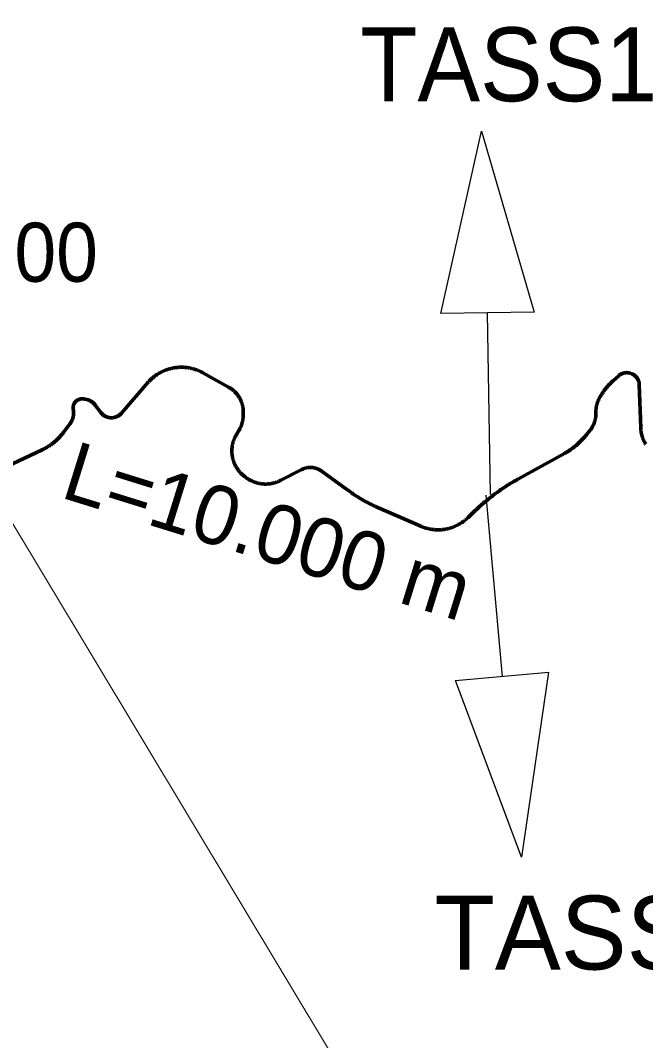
# Model space of a CAD drawing. Extents: x -1643653 to 4543381, y 1624270 to 13878484.
# Drawn here: x 592913 to 597147, y 8961770 to 8968678 of the extents above; entities that cross this region are included whole.
import ezdxf
from ezdxf.enums import TextEntityAlignment as Align

# ---------------------------------------------------------------- set-up
doc = ezdxf.new("R2010")
doc.units = 0
doc.header["$LTSCALE"] = 160
for name, color, linetype, lineweight in [('15', 7, 'Continuous', 25), ('50', 7, 'Continuous', 13), ('54', 7, 'Continuous', 25), ('60', 7, 'Continuous', 13), ('61', 7, 'Continuous', 70)]:
    doc.layers.add(name, color=color, linetype=linetype, lineweight=lineweight)

msp = doc.modelspace()

# ---------------------------------------------------------------- linework, layer by layer
at = {"layer": '50'}
msp.add_lwpolyline([(592100.1, 8966535.4), (596008.5, 8960032.9), (592886.1, 8960032.9)], dxfattribs=at)
at = {"layer": '54'}
for p, q in [((596096.5, 8965467.2), (596076.8, 8966698.1)), ((596064.8, 8965462.2), (596175, 8964236.1))]:
    msp.add_line(p, q, dxfattribs=at)
for points in [[(595761, 8966693.1), (596034.8, 8967928.7), (596392.5, 8966703.2)], [(596489.5, 8964264.3), (596307.4, 8963011.9), (595860.5, 8964207.8)]]:
    msp.add_lwpolyline(points, close=True, dxfattribs=at)
at = {"layer": '60', "lineweight": 25}
msp.add_spline([(814781, 9009175.5), (814787.2, 9009173.4), (814796.9, 9009173.4), (814799.4, 9009172.4), (814805.1, 9009174.5), (814805.6, 9009176.5), (814811.7, 9009179.5), (814811.7, 9009179.5), (814801.5, 9009181), (814790.7, 9009181.5), (814784.1, 9009183.1), (814777.4, 9009185.1), (814778.4, 9009175.5)], degree=3, dxfattribs=at)
at = {"layer": '61'}
for points in [[(593875.9, 8966300.6), (593871.5, 8966298.5), (593867.1, 8966296.3), (593862.8, 8966294), (593858.5, 8966291.7), (593854.2, 8966289.3), (593850, 8966286.8), (593845.8, 8966284.3), (593841.6, 8966281.7), (593837.5, 8966279), (593833.5, 8966276.3), (593829.4, 8966273.5), (593825.5, 8966270.6), (593821.6, 8966267.6), (593817.7, 8966264.6), (593813.9, 8966261.6), (593810.1, 8966258.5), (593806.4, 8966255.3), (593802.7, 8966252), (593799.1, 8966248.7), (593795.5, 8966245.3), (593792, 8966241.9), (593788.6, 8966238.4), (593785.2, 8966234.9), (593781.9, 8966231.3), (593778.6, 8966227.7), (593776.4, 8966225.2), (593597.7, 8966018.2), (593595.9, 8966016.2), (593594.1, 8966014.3), (593592.2, 8966012.4), (593590.2, 8966010.5), (593588.2, 8966008.8), (593586.2, 8966007), (593584.1, 8966005.4), (593581.9, 8966003.8), (593579.7, 8966002.3), (593577.4, 8966000.8), (593575.1, 8965999.4), (593572.8, 8965998.1), (593570.4, 8965996.8), (593568, 8965995.7), (593565.6, 8965994.5), (593563.1, 8965993.5), (593560.6, 8965992.5), (593558.1, 8965991.7), (593555.5, 8965990.8), (593552.9, 8965990.1), (593550.3, 8965989.5), (593547.7, 8965988.9), (593545.1, 8965988.4), (593542.4, 8965988), (593539.8, 8965987.6), (593537.1, 8965987.3), (593534.4, 8965987.2), (593531.7, 8965987.1), (593529.1, 8965987), (593526.4, 8965987.1), (593523.7, 8965987.2), (593521, 8965987.4), (593518.3, 8965987.7), (593515.7, 8965988.1), (593513, 8965988.6), (593510.4, 8965989.1), (593507.8, 8965989.7), (593505.2, 8965990.4), (593502.6, 8965991.2), (593500.1, 8965992), (593497.6, 8965992.9), (593495.1, 8965993.9), (593492.6, 8965995), (593490.2, 8965996.1), (593487.8, 8965997.3), (593485.4, 8965998.6), (593483.1, 8966000), (593480.8, 8966001.4), (593478.6, 8966002.9), (593476.4, 8966004.4), (593474.3, 8966006.1), (593472.2, 8966007.7), (593470.1, 8966009.5), (593468.2, 8966011.3), (593466.2, 8966013.1), (593464.3, 8966015.1), (593462.5, 8966017), (593460.8, 8966019.1), (593459.1, 8966021.1), (593457.8, 8966022.7), (593419.8, 8966073), (593418, 8966075.2), (593416.2, 8966077.5), (593414.3, 8966079.7), (593412.3, 8966081.8), (593410.3, 8966083.9), (593408.2, 8966085.9), (593406.1, 8966087.8), (593403.9, 8966089.8), (593401.6, 8966091.6), (593399.3, 8966093.4), (593397, 8966095.1), (593394.6, 8966096.7)], [(594416.1, 8966074.9), (594415, 8966078.7), (594413.9, 8966082.5), (594412.7, 8966086.3), (594411.4, 8966090), (594410, 8966093.7), (594408.6, 8966097.4), (594407.1, 8966101), (594405.5, 8966104.6), (594403.8, 8966108.2), (594402.1, 8966111.8), (594400.3, 8966115.3), (594398.4, 8966118.8), (594396.5, 8966122.2), (594394.4, 8966125.6), (594392.4, 8966129), (594390.2, 8966132.3), (594388, 8966135.5), (594385.7, 8966138.8), (594383.4, 8966141.9), (594381, 8966145.1), (594378.5, 8966148.1), (594375.9, 8966151.2), (594373.3, 8966154.1), (594370.7, 8966157.1), (594368, 8966159.9), (594365.2, 8966162.7), (594362.4, 8966165.5), (594359.5, 8966168.2), (594356.5, 8966170.8), (594353.5, 8966173.4), (594350.5, 8966175.9), (594347.4, 8966178.4), (594344.3, 8966180.8), (594341.1, 8966183.1), (594337.8, 8966185.4), (594334.6, 8966187.6), (594331.2, 8966189.7), (594327.9, 8966191.8), (594324.5, 8966193.8), (594322.6, 8966194.8), (594322.6, 8966194.8), (594149.4, 8966291.2), (594145.1, 8966293.6), (594140.7, 8966295.8), (594136.4, 8966298), (594132, 8966300.2), (594127.5, 8966302.2), (594123, 8966304.2), (594118.5, 8966306.1), (594114, 8966308), (594109.4, 8966309.8), (594104.8, 8966311.4), (594100.2, 8966313.1), (594095.6, 8966314.6), (594090.9, 8966316.1), (594086.2, 8966317.5), (594081.5, 8966318.8), (594076.7, 8966320), (594072, 8966321.2), (594067.2, 8966322.2), (594062.4, 8966323.2), (594057.6, 8966324.2), (594052.8, 8966325), (594047.9, 8966325.8), (594043.1, 8966326.5), (594038.2, 8966327.1), (594033.3, 8966327.6), (594028.5, 8966328), (594023.6, 8966328.4), (594018.7, 8966328.7), (594013.8, 8966328.9), (594008.9, 8966329), (594004, 8966329.1), (593999.1, 8966329.1), (593994.2, 8966328.9), (593989.3, 8966328.8), (593984.4, 8966328.5), (593979.5, 8966328.1), (593974.6, 8966327.7), (593969.8, 8966327.2), (593964.9, 8966326.6), (593960, 8966325.9), (593955.2, 8966325.2), (593950.4, 8966324.3), (593945.6, 8966323.4), (593940.8, 8966322.5), (593936, 8966321.4), (593931.2, 8966320.3), (593926.5, 8966319), (593921.7, 8966317.7), (593917, 8966316.4), (593912.4, 8966314.9), (593907.7, 8966313.4), (593903.1, 8966311.8), (593898.5, 8966310.1), (593893.9, 8966308.4), (593889.3, 8966306.5), (593884.8, 8966304.6), (593880.3, 8966302.7), (593875.9, 8966300.6)], [(597148.7, 8965807.3), (597146.4, 8965810.8), (597144.2, 8965814.4), (597142.2, 8965818), (597140.1, 8965821.6), (597138.2, 8965825.2), (597136.3, 8965828.9), (597134.5, 8965832.6), (597132.7, 8965836.4), (597131, 8965840.2), (597129.4, 8965844), (597127.9, 8965847.9), (597126.5, 8965851.8), (597125.1, 8965855.7), (597123.8, 8965859.6), (597122.6, 8965863.6), (597121.4, 8965867.6), (597120.3, 8965871.6), (597119.3, 8965875.6), (597118.4, 8965879.6), (597117.6, 8965883.7), (597116.8, 8965887.8), (597116.2, 8965891.9), (597115.6, 8965896), (597115.1, 8965900.1), (597114.6, 8965904.2), (597114.2, 8965908.3), (597114, 8965912.5), (597113.8, 8965916.6), (597113.7, 8965917.8), (597103.8, 8966212.4), (597103.7, 8966215), (597103.5, 8966217.5), (597103.2, 8966220), (597102.8, 8966222.5), (597102.4, 8966225), (597101.9, 8966227.5), (597101.3, 8966229.9), (597100.6, 8966232.3), (597099.9, 8966234.8), (597099, 8966237.2), (597098.1, 8966239.5), (597097.2, 8966241.8), (597096.1, 8966244.2), (597095, 8966246.4), (597093.8, 8966248.6), (597092.5, 8966250.8), (597091.2, 8966253), (597089.8, 8966255.1), (597088.3, 8966257.2), (597086.8, 8966259.2), (597085.2, 8966261.1), (597083.5, 8966263), (597081.8, 8966264.9), (597080, 8966266.7), (597078.2, 8966268.5), (597076.3, 8966270.1), (597074.4, 8966271.8), (597072.4, 8966273.3), (597070.4, 8966274.8), (597068.3, 8966276.3), (597066.2, 8966277.7), (597064, 8966279), (597061.8, 8966280.2), (597059.5, 8966281.3), (597057.3, 8966282.4), (597054.9, 8966283.5), (597052.6, 8966284.4), (597050.5, 8966285.2), (597050.5, 8966285.2), (597041.8, 8966288.2), (597039.5, 8966289), (597037.2, 8966289.7), (597034.8, 8966290.3), (597032.4, 8966290.9), (597030, 8966291.4), (597027.6, 8966291.8), (597025.1, 8966292.1), (597022.7, 8966292.3), (597020.3, 8966292.4), (597017.8, 8966292.5), (597015.4, 8966292.5), (597012.9, 8966292.4), (597010.5, 8966292.2), (597008, 8966292), (597005.6, 8966291.7), (597003.2, 8966291.3), (597000.8, 8966290.8), (596998.4, 8966290.2), (596996, 8966289.6), (596993.7, 8966288.8), (596991.4, 8966288.1), (596989.1, 8966287.2), (596986.8, 8966286.2), (596984.6, 8966285.2), (596982.4, 8966284.1), (596980.2, 8966283), (596978.1, 8966281.8), (596976.1, 8966280.5), (596974, 8966279.1), (596972, 8966277.7)], [(596972, 8966277.7), (596970.1, 8966276.2), (596968.2, 8966274.6), (596966.9, 8966273.5), (596966.9, 8966273.5), (596927.1, 8966238), (596927.1, 8966238), (596922.8, 8966234), (596918.5, 8966230), (596914.2, 8966226), (596910.1, 8966221.9), (596905.9, 8966217.7), (596901.9, 8966213.5), (596897.8, 8966209.2), (596893.9, 8966204.9), (596890, 8966200.5), (596886.2, 8966196), (596882.4, 8966191.6), (596878.7, 8966187), (596875, 8966182.4), (596871.4, 8966177.8), (596867.9, 8966173.1), (596864.5, 8966168.3), (596861.1, 8966163.6), (596857.7, 8966158.7), (596854.5, 8966153.9), (596851.3, 8966149), (596848.2, 8966144), (596845.6, 8966139.8), (596845.6, 8966139.8), (596837.5, 8966126.4), (596837.5, 8966126.4), (596835.5, 8966123), (596833.6, 8966119.6), (596831.7, 8966116.2), (596829.9, 8966112.7), (596828.2, 8966109.2), (596826.6, 8966105.7), (596825.1, 8966102.1), (596823.6, 8966098.5), (596822.2, 8966094.8), (596820.8, 8966091.2), (596819.6, 8966087.5), (596818.4, 8966083.8), (596817.3, 8966080), (596816.2, 8966076.3), (596815.3, 8966072.5), (596814.4, 8966068.7), (596813.6, 8966064.9), (596812.9, 8966061), (596812.3, 8966057.2), (596811.7, 8966053.3), (596811.2, 8966049.5), (596810.8, 8966045.6), (596810.5, 8966041.7), (596810.2, 8966037.8), (596810.1, 8966033.9), (596810, 8966030), (596810, 8966028), (596810, 8966016.1), (596810, 8966016.1), (596810, 8966012.3), (596809.8, 8966008.4), (596809.6, 8966004.6), (596809.4, 8966000.8), (596809, 8965996.9), (596808.6, 8965993.1), (596808, 8965989.3), (596807.5, 8965985.5), (596806.8, 8965981.7), (596806, 8965977.9), (596805.2, 8965974.2), (596804.3, 8965970.5), (596803.3, 8965966.7), (596802.2, 8965963), (596801.1, 8965959.4), (596799.8, 8965955.7), (596798.6, 8965952.1), (596797.2, 8965948.5), (596795.8, 8965944.9), (596794.2, 8965941.4), (596792.6, 8965937.9), (596791, 8965934.4), (596789.2, 8965931), (596787.4, 8965927.6), (596785.6, 8965924.2), (596783.6, 8965920.9), (596781.6, 8965917.6), (596779.5, 8965914.4), (596777.4, 8965911.2), (596775.2, 8965908.1), (596772.9, 8965905), (596770.5, 8965901.9), (596769.2, 8965900.2), (596769.2, 8965900.2), (596744.7, 8965869.8), (596744.7, 8965869.8), (596740.7, 8965864.8), (596736.6, 8965860), (596732.5, 8965855.2), (596728.3, 8965850.4)], [(593394.6, 8966096.7), (593392.2, 8966098.3), (593389.7, 8966099.8), (593387.2, 8966101.3), (593384.7, 8966102.7), (593382.1, 8966104), (593379.5, 8966105.2), (593376.8, 8966106.4), (593374.1, 8966107.4), (593371.4, 8966108.5), (593368.7, 8966109.4), (593365.9, 8966110.2), (593363.1, 8966111), (593360.3, 8966111.8), (593357.5, 8966112.4), (593354.6, 8966112.9), (593351.8, 8966113.4), (593348.9, 8966113.8), (593346, 8966114.1), (593343.4, 8966114.3), (593334.3, 8966115), (593332.1, 8966115.1), (593329.9, 8966115.1), (593327.8, 8966115.1), (593325.6, 8966114.9), (593323.4, 8966114.7), (593321.2, 8966114.4), (593319.1, 8966114.1), (593316.9, 8966113.6), (593314.8, 8966113.1), (593312.7, 8966112.5), (593310.6, 8966111.8), (593308.5, 8966111.1), (593306.5, 8966110.3), (593304.5, 8966109.4), (593302.5, 8966108.4), (593300.6, 8966107.3), (593298.7, 8966106.2), (593296.9, 8966105.1), (593295.1, 8966103.8), (593293.3, 8966102.5), (593291.6, 8966101.1), (593290, 8966099.7), (593288.4, 8966098.2), (593286.8, 8966096.6), (593285.3, 8966095), (593283.9, 8966093.4), (593282.5, 8966091.7), (593281.2, 8966089.9), (593280, 8966088.1), (593278.8, 8966086.2), (593277.7, 8966084.3), (593276.7, 8966082.4), (593275.7, 8966080.4), (593274.8, 8966078.4), (593274, 8966076.4), (593273.3, 8966074.3), (593272.6, 8966072.3), (593272, 8966070.1), (593271.5, 8966068), (593271.1, 8966065.9), (593270.7, 8966063.7), (593270.5, 8966061.5), (593270.3, 8966059.3), (593270.2, 8966057.2), (593270.1, 8966055), (593270.2, 8966052.8), (593270.3, 8966050.6), (593270.5, 8966048.4), (593270.5, 8966048.1), (593272.6, 8966030.9), (593272.9, 8966027.9), (593273.1, 8966024.8), (593273.3, 8966021.8), (593273.3, 8966018.8), (593273.3, 8966015.7), (593273.3, 8966012.7), (593273.1, 8966009.7), (593272.9, 8966006.7), (593272.5, 8966003.6), (593272.1, 8966000.6), (593271.7, 8965997.6), (593271.1, 8965994.7), (593270.5, 8965991.7), (593269.7, 8965988.8), (593269, 8965985.8), (593268.1, 8965982.9), (593267.1, 8965980), (593266.1, 8965977.2), (593265, 8965974.3), (593263.8, 8965971.6), (593262.6, 8965968.8), (593261.3, 8965966.1), (593259.9, 8965963.4), (593258.4, 8965960.7), (593256.9, 8965958.1), (593255.3, 8965955.5), (593253.6, 8965953), (593251.9, 8965950.5), (593250.2, 8965948.1), (593202.9, 8965885.4)], [(594371.7, 8965658.3), (594369.8, 8965662), (594367.9, 8965665.6), (594366, 8965669.4), (594364.3, 8965673.1), (594362.6, 8965676.9), (594361, 8965680.8), (594359.5, 8965684.6), (594358, 8965688.5), (594356.7, 8965692.4), (594355.3, 8965696.3), (594354.1, 8965700.3), (594353, 8965704.3), (594351.9, 8965708.3), (594350.9, 8965712.3), (594350, 8965716.4), (594349.1, 8965720.4), (594348.4, 8965724.5), (594347.7, 8965728.6), (594347.1, 8965732.7), (594346.6, 8965736.8), (594346.1, 8965740.9), (594345.8, 8965745.1), (594345.5, 8965749.2), (594345.3, 8965753.3), (594345.2, 8965757.5), (594345.1, 8965761.6), (594345.1, 8965765.8), (594345.2, 8965769.9), (594345.4, 8965774.1), (594345.7, 8965778.2), (594346.1, 8965782.3), (594346.5, 8965786.5), (594347, 8965790.6), (594347.6, 8965794.7), (594348.3, 8965798.8), (594349, 8965802.8), (594349.9, 8965806.9), (594350.8, 8965811), (594351.8, 8965815), (594352.8, 8965819), (594354, 8965823), (594355.2, 8965827), (594356.5, 8965830.9), (594357.8, 8965834.8), (594359.3, 8965838.7), (594360.8, 8965842.6), (594362.4, 8965846.4), (594364.1, 8965850.2), (594365.8, 8965854), (594367.6, 8965857.7), (594369.5, 8965861.4), (594371.4, 8965865), (594373.5, 8965868.7), (594375.6, 8965872.2), (594376.4, 8965873.7), (594392.3, 8965899.8), (594392.3, 8965899.8), (594394.3, 8965903.2), (594396.3, 8965906.7), (594398.2, 8965910.2), (594400.1, 8965913.8), (594401.8, 8965917.3), (594403.5, 8965921), (594405.1, 8965924.6), (594406.7, 8965928.3), (594408.2, 8965932), (594409.6, 8965935.8), (594410.9, 8965939.6), (594412.1, 8965943.4), (594413.3, 8965947.2), (594414.4, 8965951), (594415.4, 8965954.9), (594416.3, 8965958.8), (594417.2, 8965962.7), (594418, 8965966.6), (594418.7, 8965970.6), (594419.3, 8965974.5), (594419.8, 8965978.5), (594420.3, 8965982.5), (594420.7, 8965986.4), (594421, 8965990.4), (594421.1, 8965991.3), (594421.1, 8965991.3), (594422.4, 8966012.3), (594422.6, 8966016.2), (594422.7, 8966020.2), (594422.8, 8966024.2), (594422.7, 8966028.1), (594422.6, 8966032.1), (594422.4, 8966036), (594422.1, 8966039.9), (594421.8, 8966043.9), (594421.3, 8966047.8), (594420.8, 8966051.7), (594420.2, 8966055.6), (594419.6, 8966059.5), (594418.8, 8966063.4), (594418, 8966067.2), (594417.1, 8966071.1), (594416.1, 8966074.9)], [(593202.9, 8965885.4), (593199.5, 8965881), (593196.1, 8965876.7), (593192.6, 8965872.4), (593189.1, 8965868.2), (593185.5, 8965864), (593181.8, 8965859.9), (593178.1, 8965855.8), (593174.3, 8965851.8), (593170.5, 8965847.8), (593166.6, 8965843.9), (593162.7, 8965840.1), (593158.6, 8965836.3), (593154.6, 8965832.6), (593150.5, 8965828.9), (593146.3, 8965825.3), (593142.1, 8965821.7), (593137.8, 8965818.2), (593133.5, 8965814.8), (593129.1, 8965811.5), (593124.7, 8965808.2), (593120.2, 8965804.9), (593115.7, 8965801.8), (593111.2, 8965798.7), (593106.6, 8965795.6), (593101.9, 8965792.6), (593097.2, 8965789.7), (593092.5, 8965786.9), (593087.8, 8965784.1), (593082.9, 8965781.4), (593078.1, 8965778.8), (593073.2, 8965776.3), (593068.3, 8965773.8), (593063.3, 8965771.4), (593060.5, 8965770), (592704.5, 8965603.5)], [(596728.3, 8965850.4), (596724.1, 8965845.7), (596719.8, 8965841.1), (596715.5, 8965836.5), (596711.1, 8965832), (596706.6, 8965827.5), (596702.1, 8965823.1), (596697.5, 8965818.7), (596692.8, 8965814.4), (596688.2, 8965810.2), (596683.4, 8965806), (596678.6, 8965801.9), (596673.8, 8965797.8), (596668.9, 8965793.8), (596663.9, 8965789.9), (596658.9, 8965786), (596653.9, 8965782.2), (596648.8, 8965778.4), (596643.6, 8965774.7), (596638.5, 8965771.1), (596633.2, 8965767.6), (596628, 8965764.1), (596622.6, 8965760.7), (596617.3, 8965757.3), (596611.9, 8965754), (596606.4, 8965750.8), (596600.9, 8965747.7), (596596.8, 8965745.4), (596596.8, 8965745.4), (596285.6, 8965573.4), (596285.6, 8965573.4), (596276.2, 8965568.2), (596266.9, 8965562.9), (596257.6, 8965557.5), (596248.4, 8965552.1), (596239.2, 8965546.6), (596230.1, 8965541.1), (596221, 8965535.4), (596211.9, 8965529.8), (596202.9, 8965524), (596194, 8965518.2), (596185, 8965512.3), (596176.2, 8965506.3), (596167.3, 8965500.3), (596158.5, 8965494.2), (596149.8, 8965488.1), (596141.1, 8965481.8), (596132.4, 8965475.5), (596123.8, 8965469.2), (596115.2, 8965462.8), (596106.7, 8965456.3), (596098.3, 8965449.8), (596089.9, 8965443.2), (596081.5, 8965436.5), (596073.2, 8965429.8), (596064.9, 8965423), (596056.7, 8965416.1), (596048.6, 8965409.2), (596040.5, 8965402.2), (596032.4, 8965395.2), (596024.4, 8965388.1), (596016.5, 8965380.9), (596008.6, 8965373.7), (596000.7, 8965366.4), (595992.9, 8965359.1), (595985.2, 8965351.7), (595977.5, 8965344.3), (595972.7, 8965339.5), (595944.8, 8965312), (595944.8, 8965312), (595941.3, 8965308.6), (595937.8, 8965305.3), (595934.2, 8965302.1), (595930.6, 8965298.9), (595926.9, 8965295.8), (595923.2, 8965292.7), (595919.4, 8965289.7), (595915.6, 8965286.8), (595911.8, 8965283.9), (595907.8, 8965281.1), (595903.9, 8965278.4), (595899.9, 8965275.7), (595895.8, 8965273.1), (595891.7, 8965270.6), (595887.6, 8965268.1), (595883.4, 8965265.7), (595879.2, 8965263.4), (595874.9, 8965261.1), (595870.6, 8965258.9), (595866.3, 8965256.8), (595862, 8965254.8), (595857.6, 8965252.8), (595853.1, 8965250.9), (595848.7, 8965249.1), (595844.2, 8965247.3), (595839.7, 8965245.6), (595835.1, 8965244), (595830.6, 8965242.5), (595826, 8965241.1), (595821.3, 8965239.7), (595816.7, 8965238.4)], [(594860.1, 8965649.8), (594857, 8965649.3), (594853.9, 8965648.8), (594850.8, 8965648.2), (594847.7, 8965647.5), (594844.6, 8965646.7), (594841.6, 8965645.9), (594838.6, 8965645), (594835.6, 8965643.9), (594832.6, 8965642.9), (594829.7, 8965641.7), (594826.7, 8965640.5), (594823.8, 8965639.2), (594821, 8965637.8), (594819.9, 8965637.3), (594673.2, 8965562.4), (594673.2, 8965562.4), (594669.5, 8965560.5), (594665.7, 8965558.7), (594661.9, 8965557), (594658, 8965555.3), (594654.1, 8965553.8), (594650.2, 8965552.2), (594646.3, 8965550.8), (594642.3, 8965549.5), (594638.3, 8965548.2), (594634.3, 8965547), (594630.2, 8965545.8), (594626.2, 8965544.8), (594622.1, 8965543.8), (594618, 8965542.9), (594613.9, 8965542.1), (594609.8, 8965541.4), (594605.6, 8965540.7), (594601.5, 8965540.2), (594597.3, 8965539.7), (594593.1, 8965539.2), (594588.9, 8965538.9), (594584.7, 8965538.6), (594580.6, 8965538.5), (594576.3, 8965538.4), (594572.2, 8965538.3), (594568, 8965538.4), (594563.8, 8965538.5), (594559.6, 8965538.8), (594555.4, 8965539.1), (594551.2, 8965539.4), (594547.1, 8965539.9), (594542.9, 8965540.4), (594538.7, 8965541.1), (594534.6, 8965541.8), (594530.5, 8965542.5), (594526.4, 8965543.4), (594522.3, 8965544.3), (594518.2, 8965545.3), (594514.2, 8965546.4), (594510.1, 8965547.6), (594506.1, 8965548.8), (594502.1, 8965550.1), (594498.2, 8965551.5), (594494.2, 8965553), (594490.3, 8965554.5), (594486.5, 8965556.2), (594482.6, 8965557.8), (594478.8, 8965559.6), (594475.1, 8965561.5), (594471.3, 8965563.4), (594467.6, 8965565.3), (594464, 8965567.4), (594460.3, 8965569.5), (594456.8, 8965571.7), (594453.2, 8965573.9), (594449.7, 8965576.3), (594446.3, 8965578.7), (594442.9, 8965581.1), (594441.2, 8965582.3), (594441.2, 8965582.3), (594431.1, 8965589.9), (594431.1, 8965589.9), (594427.8, 8965592.5), (594424.6, 8965595), (594421.4, 8965597.7), (594418.2, 8965600.4), (594415.1, 8965603.2), (594412.1, 8965606), (594409.1, 8965608.9), (594406.2, 8965611.8), (594403.3, 8965614.8), (594400.5, 8965617.8), (594397.8, 8965621), (594395.1, 8965624.1), (594392.5, 8965627.3), (594389.9, 8965630.6), (594387.4, 8965633.9), (594385, 8965637.2), (594382.6, 8965640.6), (594380.3, 8965644.1), (594378, 8965647.6), (594375.9, 8965651.1), (594373.8, 8965654.7), (594371.7, 8965658.3)], [(595816.7, 8965238.4), (595812.1, 8965237.2), (595807.4, 8965236), (595802.7, 8965235), (595798, 8965234), (595793.2, 8965233.1), (595788.5, 8965232.2), (595783.7, 8965231.5), (595779, 8965230.8), (595774.2, 8965230.2), (595769.4, 8965229.7), (595764.6, 8965229.3), (595759.8, 8965229), (595755, 8965228.7), (595750.2, 8965228.5), (595745.3, 8965228.4), (595740.5, 8965228.3), (595735.7, 8965228.4), (595730.9, 8965228.5), (595726.1, 8965228.7), (595721.3, 8965229), (595716.5, 8965229.4), (595711.7, 8965229.8), (595706.9, 8965230.4), (595702.1, 8965231), (595697.3, 8965231.7), (595692.6, 8965232.4), (595687.8, 8965233.3), (595683.1, 8965234.2), (595678.4, 8965235.2), (595673.7, 8965236.3), (595669, 8965237.4), (595664.4, 8965238.7), (595659.8, 8965240), (595655.1, 8965241.4), (595650.6, 8965242.8), (595646, 8965244.4), (595641.5, 8965246), (595636.9, 8965247.7), (595632.5, 8965249.4), (595628, 8965251.3), (595625, 8965252.6), (595625, 8965252.6), (595323, 8965384.4), (595323, 8965384.4), (595315, 8965387.9), (595307.1, 8965391.5), (595299.2, 8965395.2), (595291.4, 8965398.9), (595283.5, 8965402.7), (595275.8, 8965406.6), (595268, 8965410.5), (595260.3, 8965414.6), (595252.6, 8965418.7), (595245, 8965422.8), (595237.4, 8965427.1), (595229.8, 8965431.3), (595222.3, 8965435.7), (595214.8, 8965440.2), (595207.4, 8965444.7), (595200, 8965449.2), (595192.7, 8965453.9), (595185.4, 8965458.6), (595178.1, 8965463.4), (595170.9, 8965468.2), (595163.7, 8965473.1), (595156.6, 8965478.1), (595149.5, 8965483.2), (595147.8, 8965484.4), (595114.3, 8965508.6), (594950, 8965627.3), (594947.4, 8965629.1), (594944.7, 8965630.8), (594942.1, 8965632.5), (594939.3, 8965634.1), (594936.6, 8965635.7), (594933.8, 8965637.2), (594931, 8965638.6), (594928.1, 8965639.9), (594925.2, 8965641.2), (594922.2, 8965642.3), (594919.3, 8965643.5), (594916.3, 8965644.5), (594913.3, 8965645.5), (594910.3, 8965646.3), (594907.2, 8965647.2), (594904.1, 8965647.9), (594901, 8965648.6), (594897.9, 8965649.1), (594894.8, 8965649.6), (594891.7, 8965650), (594888.5, 8965650.4), (594885.4, 8965650.6), (594882.2, 8965650.8), (594879.1, 8965650.9), (594875.9, 8965650.9), (594872.7, 8965650.9), (594869.6, 8965650.7), (594866.4, 8965650.5), (594863.3, 8965650.2), (594860.1, 8965649.8)]]:
    msp.add_lwpolyline(points, dxfattribs=at)

# ---------------------------------------------------------------- texts
at = {"layer": '15', "width": 0.95}
msp.add_text('C-00', height=400, dxfattribs=at).set_placement((592336.7, 8966908))
at = {"layer": '50'}
msp.add_text('L=10.000 m', height=400, rotation=342.735, dxfattribs=at).set_placement((593174.4, 8965451))
at = {"layer": '54', "width": 0.95}
msp.add_text('TASS1', height=500, dxfattribs=at).set_placement((596220.1, 8968130.2), align=Align.CENTER)
at = {"layer": '54'}
msp.add_text('TASS2', height=500, dxfattribs=at).set_placement((596776.8, 8962251.1), align=Align.CENTER)

doc.saveas('drawing.dxf')
